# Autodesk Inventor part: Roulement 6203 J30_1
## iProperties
Author: Administrateur
Created: 2004-01
Part Number: Roulement 6203 J30_1
Material: Par défaut
Document SubType Name: Modélisation
Designer: Administrateur
Control State: 0
Master: False
Checked Out: False
PropertySet Name: Design Tracking Control
Shininess: 20.0
Angle Display Precision: 2
Document Length Units: 11269
Document Angle Units: 11283
Document Time Units: 11279
Document Mass Units: 11290
Document Length Units Precision: 3
Document Angle Units Precision: 2
Compacted: False
PropertySet Name: _Private Model Information
Density: 0.0
Volumn: 0.0
Area: 0.0
PropertySet Name: Model Information
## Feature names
1. Base1
